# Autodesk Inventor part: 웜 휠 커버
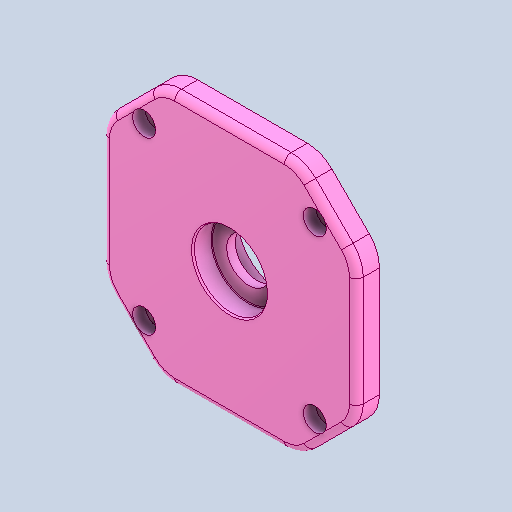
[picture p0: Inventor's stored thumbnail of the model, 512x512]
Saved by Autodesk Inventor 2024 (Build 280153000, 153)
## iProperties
Created: 2026-01
Part Number: 웜 휠 커버
Material: 알루미늄 6061
Document SubType Name: Modeling
Designer: 2-10
Density: 2.7 g/cm^3
Appearance: 기본값
Sending System: Autodesk Inventor 2026
Preprocessor: ST-DEVELOPER v20.1
Author: jhkim
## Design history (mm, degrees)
node "웜 휠 커버1"
node "솔리드2"
node "솔리드1"
